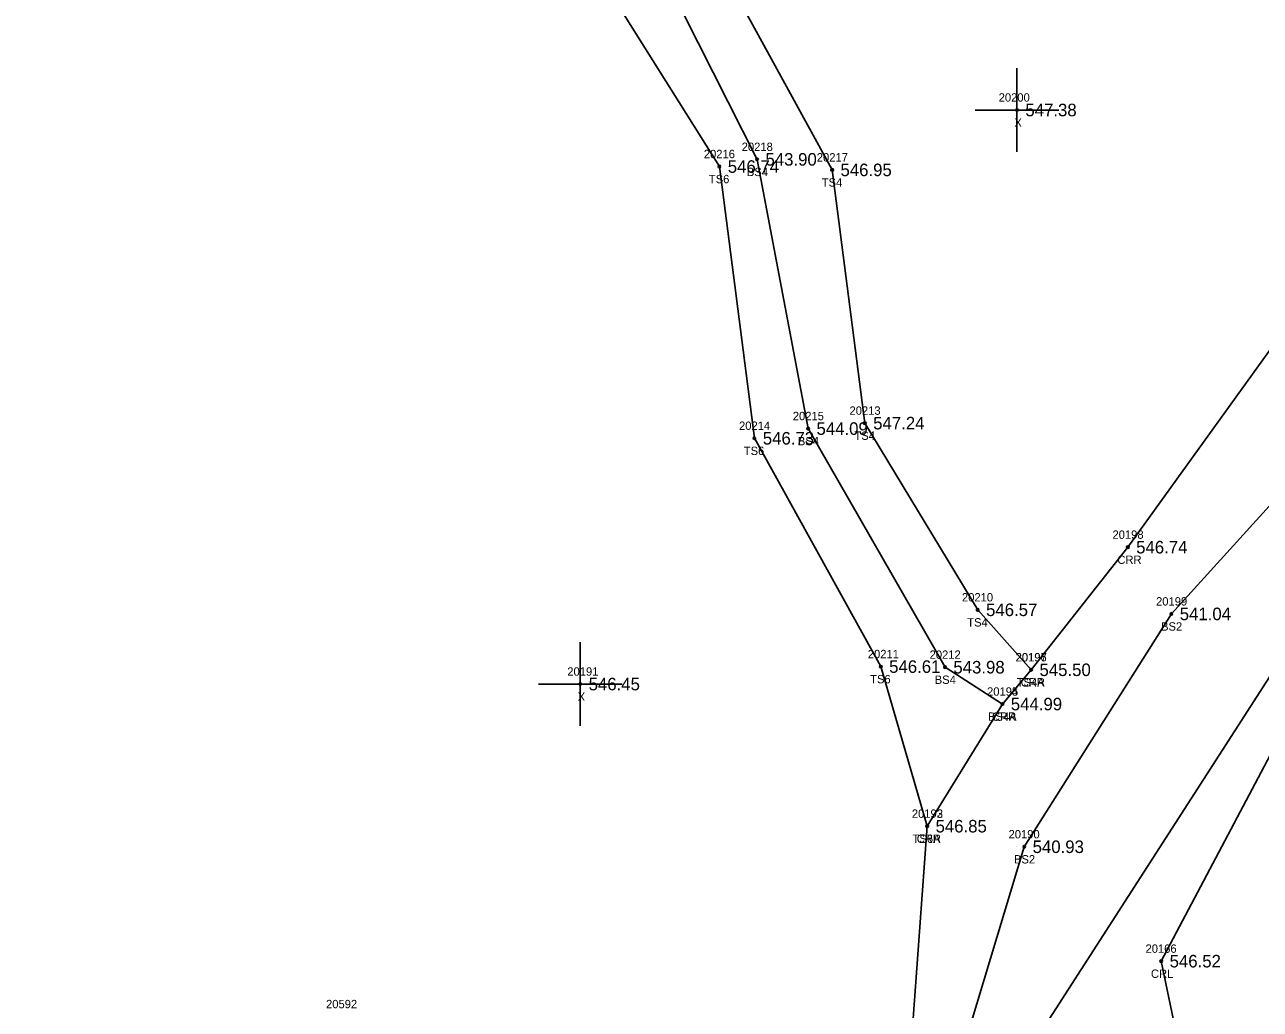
# Model space of a CAD drawing. Extents: x 1540443 to 1541844, y 887157 to 888162.
# Drawn here: x 1540989.1 to 1541136.9, y 887775.4 to 887893.1 of the extents above; entities that cross this region are included whole.
import ezdxf

# ---------------------------------------------------------------- set-up
doc = ezdxf.new("R2010")
doc.units = 0
for name, color, linetype in [('RD_DTM_BkLn2', 7, 'Continuous'), ('RD_DTM_BkLn_txCode', 7, 'Continuous'), ('RD_EX_H2O', 7, 'Continuous'), ('RD_EX_H2O_txCode', 7, 'Continuous'), ('RD_EX_Misc', 7, 'Continuous'), ('RD_EX_Misc_txCode', 7, 'Continuous'), ('RD_EX_TX_H2O_ELEV', 7, 'Continuous'), ('RD_EX_TX_Misc_ELEV', 7, 'Continuous'), ('RD_SMD_Locator', 7, 'Continuous')]:
    doc.layers.add(name, color=color, linetype=linetype)

msp = doc.modelspace()

# ---------------------------------------------------------------- linework, layer by layer
at = {"layer": 'RD_DTM_BkLn2'}
for points in [[(1541349.06, 887859.41), (1541301.9, 887838.51), (1541276.98, 887854.12), (1541250.17, 887847.68), (1541235.42, 887838.4), (1541226.46, 887818.66), (1541206.99, 887816.69), (1541177.91, 887783.05), (1541174.61, 887756.9), (1541155.39, 887744.58), (1541154.65, 887729.69), (1541126.74, 887754.56), (1541108.32, 887769.11), (1541148.46, 887831.42), (1541178.11, 887856.6), (1541159.66, 887905.22), (1541133.37, 887953.98), (1541101.85, 887998.23), (1541093.93, 888039.66), (1541072.92, 888058.86), (1541087, 888085), (1541104.04, 888122.31), (1541088.02, 888158.63)], [(1541146.1, 887665.49), (1541138.57, 887693.18), (1541134.72, 887704.76), (1541142.18, 887722.96), (1541114.88, 887744.39), (1541098.19, 887760.21), (1541108.65, 887794.85), (1541126.24, 887822.69), (1541166.01, 887866.51), (1541149.08, 887912.73), (1541115.84, 887949.01), (1541089.41, 887986.26), (1541082.08, 888036.68), (1541064.88, 888057.53), (1541079.32, 888092.84), (1541092.39, 888127.26), (1541076.18, 888157.56)], [(1541109.47, 887816.01), (1541103.08, 887823.18), (1541089.58, 887845.5), (1541085.67, 887875.78), (1541070.94, 887902.71), (1541055.37, 887955.36), (1541031.94, 887985.5), (1541025.96, 888004.59), (1541033.15, 888041.73), (1541003.69, 888062.03), (1540999.11, 888100.69)], [(1541106.04, 887811.91), (1541099.17, 887816.32), (1541082.8, 887844.85), (1541076.7, 887877.04), (1541064.39, 887901.43), (1541050.59, 887953.16), (1541026.43, 887984.19), (1541021.35, 888005.68), (1541026.22, 888039.26), (1540998.69, 888058.54), (1540993.78, 888096.72)], [(1541097.04, 887797.31), (1541091.49, 887816.39), (1541076.38, 887843.69), (1541072.19, 887876.18), (1541057.82, 887899.11), (1541044.09, 887950.3), (1541021.86, 887982.32), (1541015.45, 888004.75), (1541020.24, 888036.52), (1540992.24, 888055.16), (1540989.11, 888091.69)]]:
    msp.add_lwpolyline(points, dxfattribs=at)
at = {"layer": 'RD_EX_H2O'}
for points in [[(1541345.47, 887860.33), (1541299.81, 887843.04), (1541278.31, 887858.39), (1541248.14, 887850.88), (1541232.97, 887840.42), (1541206.44, 887819.7), (1541175.27, 887783.56), (1541168.89, 887762.72), (1541151.82, 887746.65), (1541151.42, 887737.55), (1541129.57, 887759.43), (1541125.03, 887781.17), (1541150.06, 887828.48), (1541182.67, 887854.92), (1541164.01, 887910.29), (1541139.24, 887954.07), (1541111.52, 888003.47), (1541100.67, 888047.04), (1541091.5, 888080.23), (1541107.64, 888120.67), (1541095.14, 888160.09)], [(1541139.32, 887662.55), (1541132.94, 887692.98), (1541127.99, 887710.83), (1541127.84, 887719.69), (1541112.29, 887736.27), (1541094.28, 887759.52), (1541097.04, 887797.31), (1541106.04, 887811.91), (1541109.47, 887816.01), (1541121.03, 887830.67), (1541155.26, 887878.19), (1541140.59, 887910.22), (1541112.01, 887944.26), (1541086.28, 887983.65), (1541077.88, 888035.59), (1541062.25, 888056.78), (1541074.93, 888096.19), (1541086.66, 888128.26), (1541074.68, 888157.66)]]:
    msp.add_lwpolyline(points, dxfattribs=at)
at = {"layer": 'RD_EX_Misc'}
for p, q in [((1541107.78, 887877.94), (1541107.78, 887887.94)), ((1541102.78, 887882.94), (1541112.78, 887882.94)), ((1541055.55, 887809.3), (1541055.55, 887819.3)), ((1541050.55, 887814.3), (1541060.55, 887814.3))]:
    msp.add_line(p, q, dxfattribs=at)
at = {"layer": 'RD_SMD_Locator'}
for centre in [(1541107.78, 887882.94), (1541076.7, 887877.04), (1541072.19, 887876.18), (1541085.67, 887875.78), (1541082.8, 887844.85), (1541089.58, 887845.5), (1541076.38, 887843.69), (1541121.03, 887830.67), (1541103.08, 887823.18), (1541126.24, 887822.69), (1541091.49, 887816.39), (1541099.17, 887816.32), (1541109.47, 887816.01), (1541109.47, 887816.01), (1541055.55, 887814.3), (1541106.04, 887811.91), (1541106.04, 887811.91), (1541097.04, 887797.31), (1541097.04, 887797.31), (1541108.65, 887794.85), (1541125.03, 887781.17)]:
    msp.add_circle(centre, 0.15, dxfattribs=at)

# ---------------------------------------------------------------- texts
at = {"layer": 'RD_DTM_BkLn_txCode'}
for s, p in [('20218', (1541074.86, 887878.04)), ('20216', (1541070.33, 887877.18)), ('20217', (1541083.84, 887876.78)), ('BS4', (1541075.47, 887875.04)), ('TS6', (1541070.93, 887874.18)), ('TS4', (1541084.43, 887873.78)), ('20215', (1541080.97, 887845.85)), ('20213', (1541087.75, 887846.5)), ('20214', (1541074.54, 887844.69)), ('BS4', (1541081.57, 887842.85)), ('TS4', (1541088.34, 887843.5)), ('TS6', (1541075.11, 887841.69)), ('20210', (1541101.2, 887824.18)), ('20199', (1541124.41, 887823.69)), ('TS4', (1541101.83, 887821.18)), ('BS2', (1541125.01, 887820.69)), ('20211', (1541089.94, 887817.39)), ('20212', (1541097.33, 887817.32)), ('20197', (1541107.63, 887817.01)), ('TS6', (1541090.22, 887814.39)), ('BS4', (1541097.94, 887814.32)), ('20195', (1541104.2, 887812.91)), ('TS4A', (1541107.74, 887814.01)), ('BS4A', (1541104.32, 887809.91)), ('20193', (1541095.21, 887798.31)), ('TS6A', (1541095.29, 887795.31)), ('20190', (1541106.77, 887795.85)), ('BS2', (1541107.42, 887792.85)), ('20592', (1541025.15, 887775.54))]:
    msp.add_text(s, height=1, dxfattribs=at).set_placement(p)
at = {"layer": 'RD_EX_H2O_txCode'}
for s, p in [('20198', (1541119.2, 887831.67)), ('CRR', (1541119.78, 887828.67)), ('20196', (1541107.61, 887817.01)), ('20194', (1541104.2, 887812.91)), ('CRR', (1541108.22, 887814.01)), ('CRR', (1541104.78, 887809.91)), ('20192', (1541095.21, 887798.31)), ('CRR', (1541095.79, 887795.31)), ('20166', (1541123.15, 887782.17)), ('CRL', (1541123.8, 887779.17))]:
    msp.add_text(s, height=1, dxfattribs=at).set_placement(p)
at = {"layer": 'RD_EX_Misc_txCode'}
for s, p in [('20200', (1541105.59, 887883.94)), ('X', (1541107.47, 887880.94)), ('20191', (1541054, 887815.3)), ('X', (1541055.24, 887812.3))]:
    msp.add_text(s, height=1, dxfattribs=at).set_placement(p)
at = {"layer": 'RD_EX_TX_H2O_ELEV'}
for s, p in [('546.74', (1541122.03, 887829.92)), ('545.50', (1541110.47, 887815.26)), ('544.99', (1541107.04, 887811.16)), ('546.85', (1541098.04, 887796.56)), ('546.52', (1541126.03, 887780.42))]:
    msp.add_text(s, height=1.5, dxfattribs=at).set_placement(p)
at = {"layer": 'RD_EX_TX_Misc_ELEV'}
for s, p in [('547.38', (1541108.78, 887882.19)), ('543.90', (1541077.7, 887876.29)), ('546.74', (1541073.19, 887875.43)), ('546.95', (1541086.67, 887875.03)), ('547.24', (1541090.58, 887844.75)), ('544.09', (1541083.8, 887844.1)), ('546.73', (1541077.38, 887842.94)), ('546.57', (1541104.08, 887822.43)), ('541.04', (1541127.24, 887821.94)), ('546.61', (1541092.49, 887815.64)), ('543.98', (1541100.17, 887815.57)), ('545.50', (1541110.47, 887815.26)), ('546.45', (1541056.55, 887813.55)), ('544.99', (1541107.04, 887811.16)), ('546.85', (1541098.04, 887796.56)), ('540.93', (1541109.65, 887794.1))]:
    msp.add_text(s, height=1.5, dxfattribs=at).set_placement(p)

doc.saveas('drawing.dxf')
